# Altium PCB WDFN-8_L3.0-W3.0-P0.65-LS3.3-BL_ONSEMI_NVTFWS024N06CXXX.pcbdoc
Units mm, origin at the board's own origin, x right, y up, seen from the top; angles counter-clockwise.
Board outline 16.2 x 16.94 mm, 2 copper layers (Top Layer, Bottom Layer), stack 0 mm thick; 1 components, 0 nets, 11 pads, 0 vias.
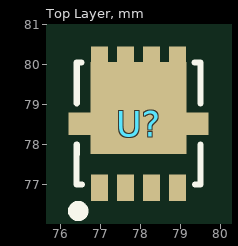
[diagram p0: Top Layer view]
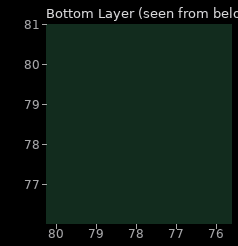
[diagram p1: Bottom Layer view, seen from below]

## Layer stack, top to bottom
Top Layer: signal copper (thickness not stored)
Bottom Layer: signal copper (thickness not stored)

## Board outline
86.05,69.85 69.85,69.85 69.85,86.787 86.05,86.787

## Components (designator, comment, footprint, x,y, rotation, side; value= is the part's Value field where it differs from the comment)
U? "" WDFN-8_L3.0-W3.0-P0.65-LS3.3-BL_ONSEMI_NVTFWS024N06CXXX 77.95,78.507 r0 top

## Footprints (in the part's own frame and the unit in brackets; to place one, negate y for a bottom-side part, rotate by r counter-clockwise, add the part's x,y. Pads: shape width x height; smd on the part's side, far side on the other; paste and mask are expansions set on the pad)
WDFN-8_L3.0-W3.0-P0.65-LS3.3-BL_ONSEMI_NVTFWS024N06CXXX [mm]
  rect 0.42x0.66 smd paste-100 mask+0.051: 1(-0.975,-1.6) 2(-0.325,-1.6) 3(0.325,-1.6) 4(0.975,-1.6) 5(0.975,1.6) 6(0.325,1.6) 7(-0.325,1.6) 8(-0.975,1.6)
  rect 0.6x0.57 smd paste-100 mask+0.051: 9(-1.45,0) 9(1.45,0)
  rect 2.4x2.3 smd paste-100 mask+0.051: 9(0,0.4)
  silkscreen extent -1.64,-2.31 1.55,1.53

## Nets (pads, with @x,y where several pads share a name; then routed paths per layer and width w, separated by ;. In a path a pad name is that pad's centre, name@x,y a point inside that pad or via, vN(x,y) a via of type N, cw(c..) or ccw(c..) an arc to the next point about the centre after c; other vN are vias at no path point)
pads on no net: U?.1 U?.2 U?.3 U?.4 U?.5 U?.6 U?.7 U?.8 U?.9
